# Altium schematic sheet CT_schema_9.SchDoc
size 277 x 170 mm
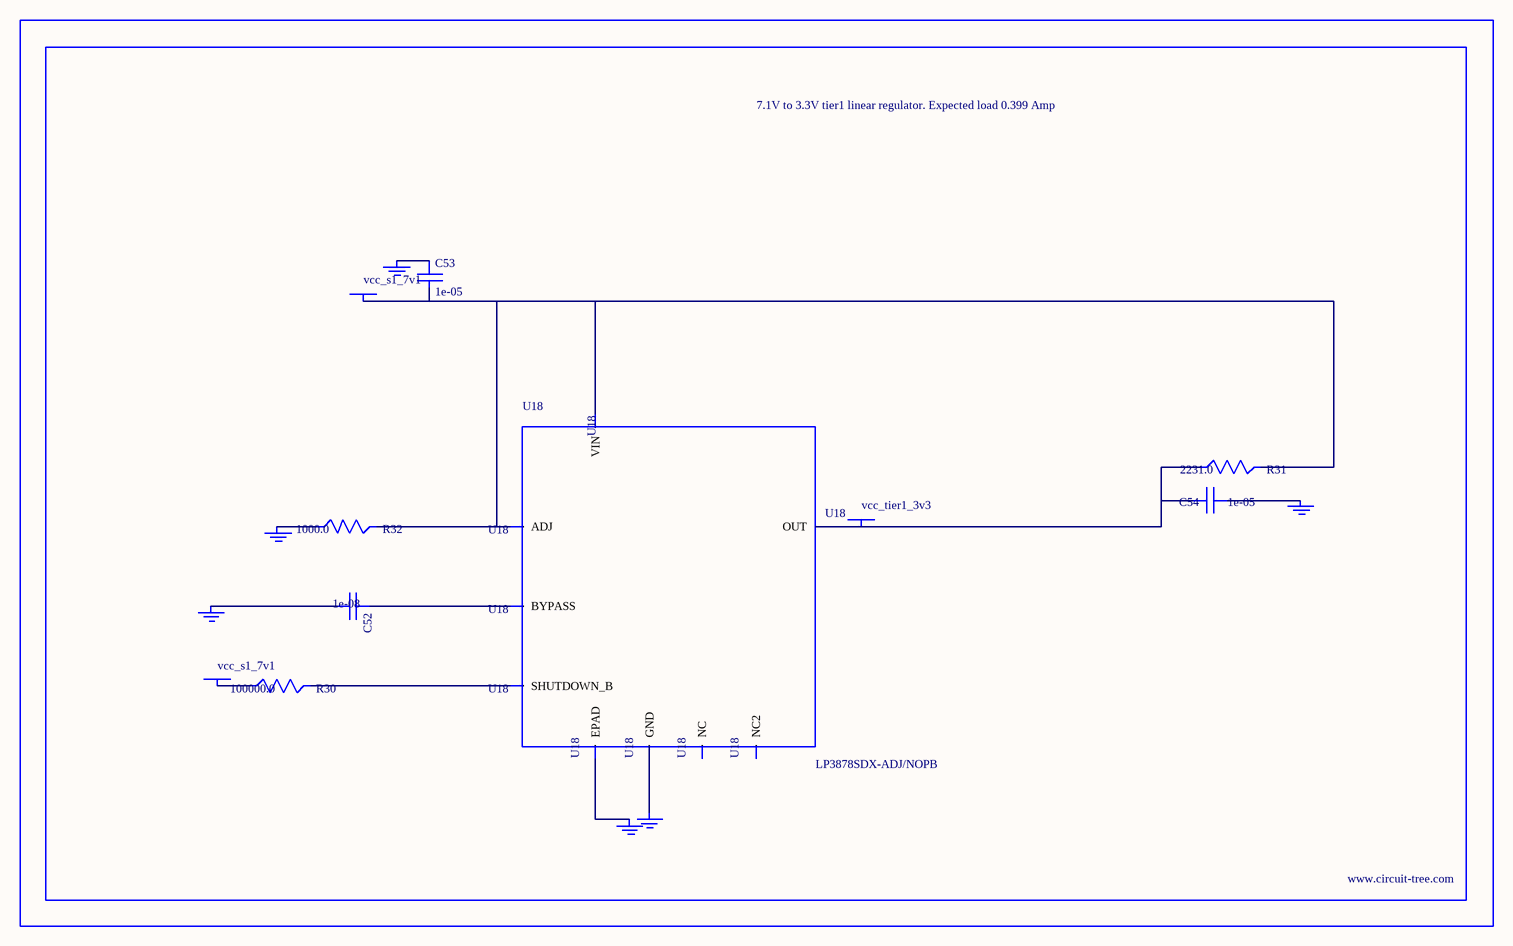
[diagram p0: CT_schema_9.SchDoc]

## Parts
BORDER8  (no value)
C52  1e-08  [C0402]
C53  1e-05  [C1206]
C54  1e-05  [C1210]
GND_INSTANCE_8_0  (no value)
GND_INSTANCE_8_1  (no value)
GND_INSTANCE_8_2  (no value)
GND_INSTANCE_8_3  (no value)
GND_INSTANCE_8_4  (no value)
GND_INSTANCE_8_5  (no value)
POWER_INSTANCE_8_0  vcc_s1_7v1
POWER_INSTANCE_8_1  vcc_s1_7v1
POWER_INSTANCE_8_2  vcc_tier1_3v3
R30  100000.0  [R0603]
R31  2231.0  [R0603]
R32  1000.0  [R0603]
U18  LP3878SDX-ADJ/NOPB  [WSON-8]

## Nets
NetC52_1: C52.1 U18.1(BYPASS)
NetC52_2: C52.2 GND_INSTANCE_8_0.0(GND)
NetC53_1: C53.1 GND_INSTANCE_8_1.0(GND)
NetC53_2: C53.2 POWER_INSTANCE_8_0.0(PWR) R31.2 R32.2 U18.4(VIN) U18.6(ADJ)
NetC54_1: C54.1 GND_INSTANCE_8_2.0(GND)
NetC54_2: C54.2 POWER_INSTANCE_8_2.0(PWR) R31.1 U18.5(OUT)
NetGND_INSTANCE_8_3_0: GND_INSTANCE_8_3.0(GND) R32.1
NetGND_INSTANCE_8_4_0: GND_INSTANCE_8_4.0(GND) U18.PAD(EPAD)
NetGND_INSTANCE_8_5_0: GND_INSTANCE_8_5.0(GND) U18.3(GND)
NetPOWER_INSTANCE_8_1_0: POWER_INSTANCE_8_1.0(PWR) R30.1
NetR30_2: R30.2 U18.8(SHUTDOWN_B)

Not connected (* = marked no-connect by the designer): U18 2(NC) 7(NC2)

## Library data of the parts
BORDER8 = BORDER_PAGE8
C52 = C0402C103K3RAC
C53 = C1206C106K3RACTU
C54 = GRM32DR61E106MA12L
GND_INSTANCE_8_0-GND_INSTANCE_8_5 = GND
POWER_INSTANCE_8_0-POWER_INSTANCE_8_2 = PWR
R30 = RC0603JR-07100KL
R31 = R31
R32 = RC0603JR-071KL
